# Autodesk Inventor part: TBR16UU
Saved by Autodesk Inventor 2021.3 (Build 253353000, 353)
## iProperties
Created: 2022-03
Part Number: TBR16UU
Material: Generic
Document SubType Name: Modeling
Designer: Administrator
Density: 1 g/cm^3
Appearance: Default
Title: TBR16UU
Author: Administrator
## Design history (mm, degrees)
feature "Body1"
feature "Body2"
feature "Body3"
feature "Body4"
body "Solid1"
body "Solid2"
body "Solid3"
body "Solid4"
